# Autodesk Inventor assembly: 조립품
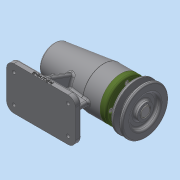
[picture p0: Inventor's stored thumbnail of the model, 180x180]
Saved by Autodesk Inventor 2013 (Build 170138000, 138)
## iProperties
Created: 2018-09
Part Number: 조립품
Document SubType Name: Assembly
Designer: dgall
Author: dgall
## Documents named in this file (12)
- C:\Users\dgall\Desktop\480907V1025\조립품.iam
- C:\Users\dgall\Desktop\480907V1025\본체.ipt
- C:\Users\dgall\Desktop\480907V1025\V벨트풀리.ipt
- C:\Users\dgall\Desktop\480907V1025\멈춤나사 M3.ipt
- C:\Users\dgall\Desktop\480907V1025\베어링 51202.ipt
- C:\Users\dgall\Desktop\480907V1025\어댑터슬리브.ipt
- C:\Users\dgall\Desktop\480907V1025\오일 실.ipt
- C:\Users\dgall\Desktop\480907V1025\축.ipt
- C:\Users\dgall\Desktop\480907V1025\커버.ipt
- C:\Users\dgall\Desktop\480907V1025\키 5 x 5 x 16.ipt
- C:\Users\dgall\Desktop\480907V1025\베어링 6004.ipt
- C:\Users\dgall\Desktop\480907V1025\볼트 M4.ipt
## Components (1 placed, 1 different names)
1. V벨트풀리:1
